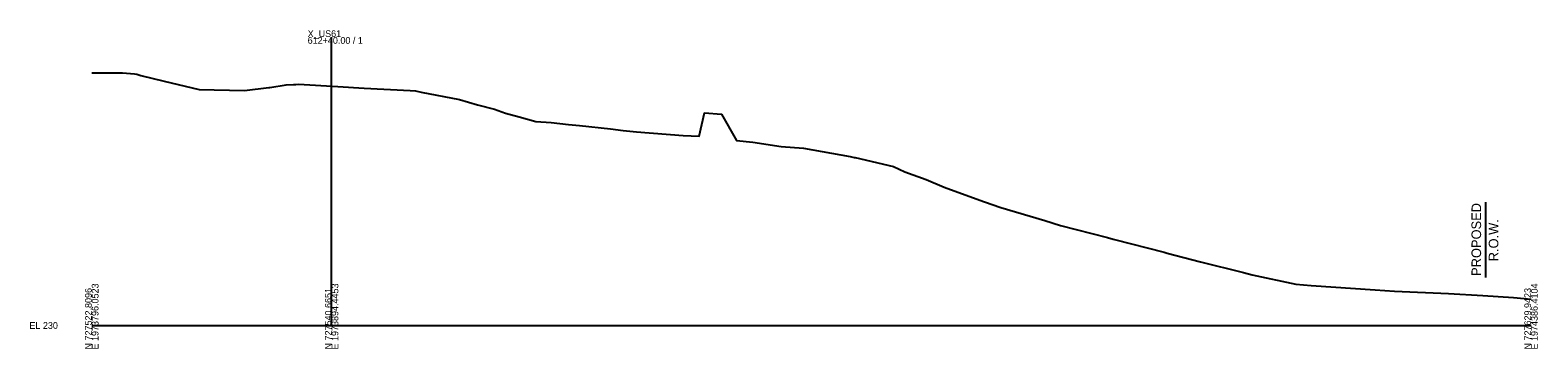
# Model space of a CAD drawing. Extents: x -26 to 1604, y -13 to 9623.
# Drawn here: x -26 to 603, y 990 to 1123 of the extents above; entities that cross this region are included whole.
import ezdxf

# ---------------------------------------------------------------- set-up
doc = ezdxf.new("R2010")
doc.units = 0
for name, color, linetype in [('Draft_XS_Grid', 7, 'Continuous'), ('DTM_X_GROUND', 7, 'Continuous'), ('XS_CELL', 7, 'Continuous'), ('XS_P_ROW', 7, 'Continuous')]:
    doc.layers.add(name, color=color, linetype=linetype)

msp = doc.modelspace()

# ---------------------------------------------------------------- linework, layer by layer
at = {"layer": 'DTM_X_GROUND'}
msp.add_lwpolyline([(0, 1105.15), (5.01, 1105.16), (12.75, 1105.18), (12.79, 1105.17), (17.85, 1104.72), (18.82, 1104.51), (20.48, 1104.07), (30.19, 1101.65), (44.76, 1098.2), (63.61, 1097.8), (73.87, 1098.97), (74.16, 1099.01), (81.09, 1100.07), (84.07, 1100.25), (85.07, 1100.31), (86.2, 1100.37), (102.56, 1099.42), (113.54, 1098.79), (132.74, 1097.72), (134.92, 1097.59), (137.27, 1097.1), (153.32, 1094), (160.83, 1091.75), (167.83, 1090.02), (172.47, 1088.31), (178.1, 1086.84), (185.11, 1084.81), (191.49, 1084.41), (198.69, 1083.56), (203.38, 1083.18), (216.18, 1081.86), (221.48, 1081.17), (227.02, 1080.63), (246.52, 1079.05), (253.16, 1078.76), (255.41, 1088.51), (262.45, 1087.92), (268.71, 1077.02), (275.58, 1076.25), (287.45, 1074.51), (296.69, 1073.82), (316.17, 1070.3), (317.79, 1069.9), (318.22, 1069.82), (334.22, 1066.13), (338.9, 1063.94), (347.9, 1060.67), (355.32, 1057.54), (362.63, 1054.93), (372.15, 1051.38), (379.02, 1049.14), (397.34, 1043.71), (403.9, 1041.66), (423.46, 1036.54), (425.75, 1035.97), (426.37, 1035.8), (447.1, 1030.44), (448.36, 1030.08), (462.24, 1026.45), (480.13, 1022.09), (483.77, 1021.07), (501.94, 1017.25), (508.36, 1016.63), (535.08, 1014.77), (543.08, 1014.31), (565.64, 1013.26), (579.92, 1012.44), (592.66, 1011.71), (600, 1010.97)], dxfattribs=at)
at = {"layer": 'XS_CELL'}
for p, q in [((100, 1000), (100, 1120)), ((0, 1000), (100, 1000)), ((100, 1000), (600, 1000))]:
    msp.add_line(p, q, dxfattribs=at)
at = {"layer": 'XS_P_ROW'}
msp.add_line((581, 1051.27), (581, 1020), dxfattribs=at)

# ---------------------------------------------------------------- texts
at = {"layer": 'Draft_XS_Grid'}
msp.add_text('-', height=0.0001, dxfattribs=at).set_placement((0, 1000))
at = {"layer": 'XS_CELL'}
for s, p in [('X_US61', (90, 1120)), ('612+40.00 / 1', (90, 1117.2)), ('EL 230', (-26, 998.6))]:
    msp.add_text(s, height=2.8, dxfattribs=at).set_placement(p)
for s, p in [('N 727522.8096', (0, 990)), ('E 1973796.0523', (2.8, 990)), ('N 727540.6651', (100, 990)), ('E 1973894.4453', (102.8, 990)), ('N 727629.9423', (600, 990)), ('E 1974386.4104', (602.8, 990))]:
    msp.add_text(s, height=2.8, rotation=90, dxfattribs=at).set_placement(p)
at = {"layer": 'XS_P_ROW'}
for s, p in [('PROPOSED', (579.18, 1020.63)), ('R.O.W.', (586.38, 1026.7))]:
    msp.add_text(s, height=4, rotation=90, dxfattribs=at).set_placement(p)

doc.saveas('drawing.dxf')
